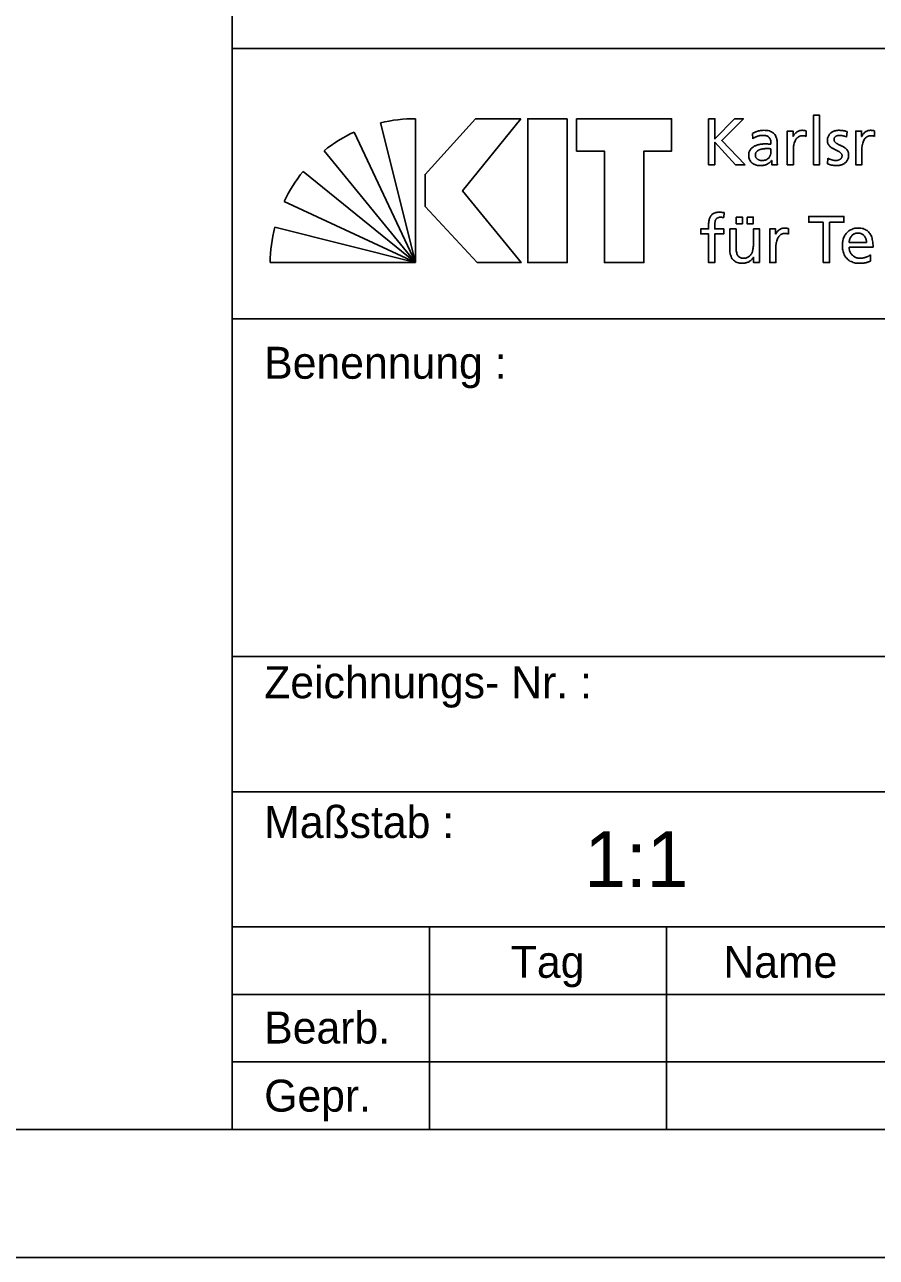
# Model space of a CAD drawing. Extents: x 0 to 420, y 0 to 297.
# Drawn here: x 315 to 368.3, y 0 to 77.2 of the extents above; entities that cross this region are included whole.
import ezdxf

# ---------------------------------------------------------------- set-up
doc = ezdxf.new("R2010")
doc.units = 0
doc.layers.add('90_Plankopf', color=7, linetype='Continuous')

msp = doc.modelspace()

# ---------------------------------------------------------------- linework, layer by layer
at = {"layer": '90_Plankopf'}
for p, q in [((328.001, 75.68), (328.001, 88.37)), ((328.001, 75.68), (412, 75.68)), ((337.275, 71.023), (339.481, 62.276)), ((339.481, 62.276), (339.481, 71.274)), ((357.81, 71.276), (357.81, 68.396)), ((339.481, 62.276), (335.633, 70.442)), ((360.579, 70.352), (360.6, 70.022)), ((363.926, 70.174), (363.926, 70.521)), ((366.457, 70.129), (366.49, 70.468)), ((368.211, 70.174), (368.211, 70.521)), ((362.118, 68.808), (362.118, 69.679)), ((333.744, 69.275), (339.481, 62.276)), ((361.73, 69.399), (361.73, 69.213)), ((365.297, 68.808), (365.277, 68.462)), ((339.481, 62.276), (332.434, 67.976)), ((357.81, 68.396), (358.222, 68.396)), ((359.506, 68.396), (360.108, 68.396)), ((331.24, 66.103), (339.481, 62.276)), ((358.773, 65.083), (358.79, 65.396)), ((339.481, 62.276), (330.658, 64.478)), ((362.827, 64.055), (362.827, 64.402)), ((367.706, 63.531), (366.616, 63.531)), ((366.616, 63.242), (368.119, 63.242)), ((367.958, 62.363), (367.958, 62.751)), ((330.364, 62.276), (339.481, 62.276)), ((328.001, 58.76), (412, 58.76)), ((328.001, 37.61), (412, 37.61)), ((328.001, 29.15), (412, 29.15)), ((328.001, 20.69), (412, 20.69)), ((328.001, 20.69), (412, 20.69)), ((328.001, 20.69), (412, 20.69)), ((328.001, 20.69), (412, 20.69)), ((328.001, 8), (328.001, 20.69)), ((340.353, 20.69), (340.353, 8)), ((355.177, 8), (355.177, 20.69)), ((328.001, 16.46), (370, 16.46)), ((328.001, 12.23), (370, 12.23)), ((328.001, 8), (412, 8)), ((328.001, 8), (411.999, 8))]:
    msp.add_line(p, q, dxfattribs=at)
for points in [[(0, 0), (420, 0), (420, 297), (0, 297)], [(8, 8), (412, 8), (412, 289), (8, 289)], [(346.066, 71.276), (343.236, 71.276), (340.073, 67.789), (340.073, 65.782), (343.338, 62.276), (346.085, 62.276), (342.422, 66.753)], [(348.97, 71.276), (348.97, 62.276), (346.501, 62.276), (346.501, 71.276)], [(349.562, 71.276), (349.562, 69.25), (351.301, 69.25), (351.301, 62.276), (353.771, 62.276), (353.771, 69.25), (355.51, 69.25), (355.51, 71.276)]]:
    msp.add_lwpolyline(points, close=True, dxfattribs=at)
for points in [[(328.001, 20.69), (328.001, 75.68)], [(360.108, 68.396), (358.647, 69.914), (360.001, 71.276), (359.452, 71.276), (358.222, 70.009), (358.222, 71.276), (357.81, 71.276)], [(364.381, 68.396), (364.768, 68.396), (364.768, 71.491), (364.381, 71.491), (364.381, 68.396)], [(363.122, 70.174), (363.113, 70.174), (363.113, 70.5), (362.75, 70.5), (362.75, 68.396), (363.138, 68.396), (363.138, 69.353)], [(367.407, 70.174), (367.398, 70.174), (367.398, 70.5), (367.035, 70.5), (367.035, 68.396), (367.423, 68.396), (367.423, 69.353)], [(358.222, 68.396), (358.222, 69.807), (359.506, 68.396)], [(361.763, 68.668), (361.772, 68.668), (361.772, 68.396), (362.135, 68.396)], [(359.554, 65.116), (359.554, 64.703), (359.942, 64.703), (359.942, 65.116), (359.554, 65.116)], [(360.231, 65.116), (360.231, 64.703), (360.619, 64.703), (360.619, 65.116), (360.231, 65.116)], [(364.99, 62.276), (365.403, 62.276), (365.403, 64.794), (366.298, 64.794), (366.298, 65.157), (364.094, 65.157), (364.094, 64.794), (364.99, 64.794), (364.99, 62.276)], [(357.824, 64.575), (357.824, 64.381), (357.329, 64.381), (357.329, 64.068), (357.824, 64.068), (357.824, 62.276), (358.212, 62.276), (358.212, 64.068), (358.769, 64.068), (358.769, 64.381), (358.212, 64.381), (358.212, 64.608)], [(359.542, 63.292), (359.542, 64.381), (359.154, 64.381), (359.154, 63.131)], [(361.015, 62.276), (361.015, 64.381), (360.627, 64.381), (360.627, 63.407)], [(362.022, 64.055), (362.014, 64.055), (362.014, 64.381), (361.651, 64.381), (361.651, 62.276), (362.039, 62.276), (362.039, 63.234)], [(360.631, 62.611), (360.639, 62.611), (360.639, 62.276), (361.015, 62.276)], [(412, 20.69), (328.001, 20.69)], [(328.001, 20.69), (328.001, 20.69)], [(328.001, 8), (412, 8)]]:
    msp.add_lwpolyline(points, dxfattribs=at)
for centre, start, end in [((339.449, 61.746), 89.80527, 103.18947), ((339.662, 61.808), 115.01261, 128.3968), ((339.816, 61.953), 140.78977, 154.17397), ((339.891, 62.128), 165.72225, 179.10644)]:
    msp.add_arc(centre, 9.528, start, end, dxfattribs=at)
for points in [[(362.118, 69.679), (362.119, 69.87), (362.091, 70.031), (362.033, 70.16), (361.975, 70.289), (361.884, 70.386), (361.759, 70.452), (361.635, 70.517), (361.472, 70.55), (361.272, 70.55), (361.138, 70.549), (361.014, 70.531), (360.898, 70.494), (360.782, 70.458), (360.676, 70.411), (360.579, 70.352)], [(360.6, 70.022), (360.653, 70.066), (360.713, 70.104), (360.779, 70.136), (360.846, 70.168), (360.916, 70.193), (360.99, 70.21), (361.063, 70.228), (361.137, 70.236), (361.21, 70.236), (361.339, 70.236), (361.441, 70.216), (361.518, 70.175), (361.594, 70.134), (361.649, 70.073), (361.682, 69.992), (361.715, 69.909), (361.731, 69.808), (361.73, 69.687)], [(363.926, 70.521), (363.899, 70.527), (363.873, 70.531), (363.849, 70.536), (363.824, 70.54), (363.798, 70.544), (363.769, 70.546), (363.741, 70.549), (363.708, 70.55), (363.67, 70.55), (363.595, 70.549), (363.523, 70.533), (363.452, 70.501), (363.382, 70.469), (363.318, 70.426), (363.261, 70.369), (363.203, 70.313), (363.157, 70.248), (363.122, 70.174)], [(366.49, 70.468), (366.414, 70.491), (366.337, 70.51), (366.259, 70.526), (366.181, 70.541), (366.097, 70.549), (366.007, 70.55), (365.903, 70.55), (365.805, 70.537), (365.716, 70.51), (365.625, 70.484), (365.547, 70.443), (365.48, 70.39), (365.412, 70.337), (365.359, 70.269), (365.322, 70.188), (365.284, 70.107), (365.265, 70.011), (365.264, 69.902), (365.265, 69.818), (365.282, 69.746), (365.315, 69.684), (365.347, 69.623), (365.391, 69.57), (365.445, 69.524), (365.5, 69.48), (365.559, 69.44), (365.623, 69.405), (365.688, 69.37), (365.753, 69.337), (365.817, 69.307), (365.882, 69.276), (365.942, 69.245), (365.995, 69.212), (366.05, 69.18), (366.093, 69.144), (366.126, 69.103), (366.158, 69.063), (366.176, 69.015), (366.176, 68.961), (366.176, 68.905), (366.163, 68.857), (366.139, 68.818), (366.116, 68.78), (366.084, 68.749), (366.045, 68.725), (366.006, 68.702), (365.963, 68.685), (365.917, 68.675), (365.871, 68.665), (365.825, 68.66), (365.78, 68.66), (365.742, 68.66), (365.695, 68.665), (365.639, 68.676), (365.584, 68.687), (365.526, 68.704), (365.466, 68.726), (365.405, 68.748), (365.35, 68.775), (365.297, 68.808)], [(365.277, 68.462), (365.366, 68.416), (365.46, 68.384), (365.558, 68.368), (365.656, 68.352), (365.755, 68.345), (365.854, 68.346), (365.949, 68.346), (366.04, 68.359), (366.127, 68.385), (366.215, 68.412), (366.293, 68.452), (366.363, 68.506), (366.431, 68.559), (366.487, 68.628), (366.527, 68.71), (366.568, 68.793), (366.588, 68.89), (366.589, 69.002), (366.588, 69.098), (366.571, 69.179), (366.539, 69.246), (366.506, 69.312), (366.462, 69.369), (366.408, 69.416), (366.354, 69.462), (366.295, 69.501), (366.23, 69.535), (366.165, 69.568), (366.101, 69.599), (366.036, 69.627), (365.971, 69.656), (365.912, 69.685), (365.858, 69.716), (365.804, 69.748), (365.76, 69.785), (365.727, 69.826), (365.695, 69.869), (365.678, 69.92), (365.677, 69.981), (365.678, 70.038), (365.696, 70.086), (365.729, 70.124), (365.763, 70.162), (365.808, 70.19), (365.864, 70.209), (365.92, 70.228), (365.982, 70.236), (366.048, 70.236), (366.072, 70.236), (366.102, 70.233), (366.139, 70.228), (366.175, 70.221), (366.213, 70.213), (366.254, 70.203), (366.295, 70.193), (366.333, 70.181), (366.369, 70.168), (366.405, 70.156), (366.434, 70.143), (366.457, 70.129)], [(368.211, 70.521), (368.184, 70.527), (368.158, 70.531), (368.134, 70.536), (368.11, 70.54), (368.083, 70.544), (368.054, 70.546), (368.026, 70.549), (367.993, 70.55), (367.955, 70.55), (367.88, 70.549), (367.808, 70.533), (367.737, 70.501), (367.667, 70.469), (367.603, 70.426), (367.546, 70.369), (367.488, 70.313), (367.442, 70.248), (367.407, 70.174)], [(361.73, 69.687), (361.68, 69.69), (361.633, 69.692), (361.589, 69.693), (361.546, 69.694), (361.502, 69.695), (361.459, 69.696), (361.415, 69.696), (361.368, 69.696), (361.318, 69.696), (361.237, 69.696), (361.151, 69.689), (361.063, 69.674), (360.973, 69.66), (360.886, 69.637), (360.801, 69.604), (360.715, 69.571), (360.638, 69.528), (360.569, 69.475), (360.499, 69.421), (360.444, 69.355), (360.403, 69.278), (360.362, 69.199), (360.341, 69.108), (360.34, 69.002), (360.341, 68.85), (360.374, 68.725), (360.439, 68.629), (360.504, 68.532), (360.594, 68.46), (360.71, 68.414), (360.825, 68.369), (360.959, 68.346), (361.111, 68.346), (361.2, 68.347), (361.28, 68.358), (361.35, 68.379), (361.421, 68.399), (361.483, 68.426), (361.536, 68.459), (361.59, 68.492), (361.635, 68.527), (361.673, 68.564), (361.71, 68.601), (361.741, 68.635), (361.763, 68.668)], [(363.138, 69.353), (363.139, 69.53), (363.163, 69.683), (363.21, 69.811), (363.257, 69.939), (363.323, 70.038), (363.409, 70.106), (363.494, 70.176), (363.595, 70.211), (363.712, 70.211), (363.746, 70.212), (363.78, 70.209), (363.818, 70.204), (363.855, 70.199), (363.891, 70.189), (363.926, 70.174)], [(367.423, 69.353), (367.424, 69.53), (367.448, 69.683), (367.495, 69.811), (367.542, 69.939), (367.608, 70.038), (367.694, 70.106), (367.779, 70.176), (367.88, 70.211), (367.997, 70.211), (368.03, 70.212), (368.065, 70.209), (368.103, 70.204), (368.14, 70.199), (368.175, 70.189), (368.211, 70.174)], [(361.73, 69.213), (361.73, 69.108), (361.708, 69.013), (361.664, 68.93), (361.62, 68.847), (361.554, 68.782), (361.467, 68.733), (361.38, 68.685), (361.272, 68.66), (361.144, 68.66), (361.1, 68.66), (361.054, 68.668), (361.008, 68.682), (360.963, 68.697), (360.92, 68.718), (360.882, 68.747), (360.843, 68.777), (360.812, 68.813), (360.789, 68.855), (360.765, 68.897), (360.753, 68.947), (360.752, 69.002), (360.754, 69.076), (360.772, 69.138), (360.808, 69.187), (360.844, 69.236), (360.891, 69.276), (360.949, 69.305), (361.007, 69.335), (361.069, 69.357), (361.135, 69.372), (361.201, 69.386), (361.265, 69.396), (361.326, 69.401), (361.387, 69.405), (361.439, 69.407), (361.483, 69.407), (361.524, 69.407), (361.565, 69.405), (361.607, 69.403), (361.648, 69.401), (361.689, 69.399), (361.73, 69.399)], [(362.135, 68.396), (362.132, 68.416), (362.129, 68.443), (362.126, 68.477), (362.125, 68.511), (362.122, 68.555), (362.121, 68.609), (362.119, 68.663), (362.118, 68.729), (362.118, 68.808)], [(358.79, 65.396), (358.751, 65.402), (358.71, 65.409), (358.668, 65.413), (358.625, 65.418), (358.579, 65.421), (358.53, 65.421), (358.388, 65.42), (358.27, 65.4), (358.178, 65.361), (358.086, 65.321), (358.014, 65.264), (357.962, 65.19), (357.91, 65.116), (357.875, 65.027), (357.854, 64.923), (357.833, 64.819), (357.824, 64.704), (357.824, 64.575)], [(358.212, 64.608), (358.212, 64.68), (358.216, 64.746), (358.224, 64.806), (358.232, 64.867), (358.249, 64.92), (358.275, 64.965), (358.3, 65.01), (358.338, 65.045), (358.388, 65.069), (358.439, 65.094), (358.505, 65.107), (358.588, 65.107), (358.621, 65.107), (358.655, 65.105), (358.688, 65.101), (358.722, 65.097), (358.75, 65.091), (358.773, 65.083)], [(362.827, 64.402), (362.8, 64.407), (362.774, 64.412), (362.75, 64.417), (362.725, 64.421), (362.698, 64.424), (362.67, 64.427), (362.642, 64.429), (362.609, 64.43), (362.571, 64.43), (362.496, 64.43), (362.423, 64.414), (362.352, 64.382), (362.282, 64.35), (362.218, 64.306), (362.161, 64.25), (362.104, 64.193), (362.057, 64.129), (362.022, 64.055)], [(362.039, 63.234), (362.039, 63.411), (362.064, 63.563), (362.11, 63.691), (362.158, 63.819), (362.224, 63.918), (362.31, 63.987), (362.395, 64.057), (362.496, 64.091), (362.612, 64.092), (362.646, 64.093), (362.681, 64.09), (362.718, 64.085), (362.756, 64.079), (362.791, 64.069), (362.827, 64.055)], [(368.119, 63.242), (368.119, 63.412), (368.103, 63.57), (368.072, 63.713), (368.041, 63.858), (367.989, 63.983), (367.918, 64.09), (367.846, 64.197), (367.751, 64.281), (367.631, 64.34), (367.512, 64.399), (367.365, 64.43), (367.19, 64.43), (367.041, 64.43), (366.906, 64.404), (366.785, 64.352), (366.665, 64.3), (366.561, 64.227), (366.474, 64.132), (366.387, 64.037), (366.321, 63.925), (366.275, 63.795), (366.228, 63.666), (366.205, 63.523), (366.204, 63.366), (366.204, 63.194), (366.225, 63.038), (366.269, 62.899), (366.312, 62.759), (366.379, 62.64), (366.469, 62.54), (366.558, 62.439), (366.671, 62.362), (366.808, 62.309), (366.945, 62.254), (367.107, 62.228), (367.293, 62.227), (367.408, 62.228), (367.506, 62.235), (367.587, 62.25), (367.667, 62.265), (367.737, 62.283), (367.797, 62.304), (367.855, 62.324), (367.909, 62.344), (367.958, 62.363)], [(366.616, 63.531), (366.623, 63.6), (366.639, 63.668), (366.664, 63.737), (366.688, 63.806), (366.722, 63.869), (366.768, 63.926), (366.812, 63.984), (366.869, 64.029), (366.937, 64.064), (367.006, 64.098), (367.087, 64.116), (367.182, 64.117), (367.266, 64.116), (367.34, 64.101), (367.404, 64.071), (367.47, 64.04), (367.524, 63.999), (367.569, 63.945), (367.614, 63.891), (367.648, 63.829), (367.671, 63.759), (367.694, 63.688), (367.706, 63.612), (367.706, 63.531)], [(360.627, 63.407), (360.627, 63.279), (360.615, 63.161), (360.589, 63.055), (360.564, 62.95), (360.525, 62.859), (360.473, 62.782), (360.421, 62.705), (360.354, 62.646), (360.273, 62.604), (360.193, 62.562), (360.097, 62.541), (359.987, 62.54), (359.875, 62.547), (359.786, 62.579), (359.721, 62.635), (359.656, 62.692), (359.61, 62.774), (359.582, 62.883), (359.554, 62.992), (359.541, 63.128), (359.542, 63.292)], [(359.154, 63.131), (359.154, 62.941), (359.181, 62.78), (359.237, 62.645), (359.293, 62.51), (359.379, 62.407), (359.496, 62.335), (359.612, 62.264), (359.761, 62.228), (359.942, 62.227), (360.04, 62.228), (360.135, 62.243), (360.225, 62.273), (360.315, 62.304), (360.396, 62.348), (360.466, 62.405), (360.537, 62.462), (360.592, 62.531), (360.631, 62.611)], [(367.958, 62.751), (367.933, 62.731), (367.899, 62.709), (367.852, 62.685), (367.806, 62.661), (367.754, 62.638), (367.694, 62.616), (367.634, 62.594), (367.572, 62.576), (367.506, 62.562), (367.44, 62.548), (367.374, 62.541), (367.309, 62.54), (367.217, 62.541), (367.13, 62.558), (367.046, 62.592), (366.964, 62.625), (366.889, 62.673), (366.825, 62.735), (366.761, 62.797), (366.71, 62.871), (366.673, 62.957), (366.636, 63.043), (366.617, 63.138), (366.616, 63.242)]]:
    msp.add_open_spline(points, degree=3, dxfattribs=at)

# ---------------------------------------------------------------- texts
for s, height, p in [('Benennung :', 2, (330, 55)), ('Zeichnungs- Nr. :', 2, (330, 35)), ('Maßstab :', 2, (330, 26.25)), ('1:1     ', 3.4999, (350.048, 23.175)), ('Tag', 2, (345.441, 17.5)), ('Name', 2, (358.75, 17.5)), ('Bearb.', 2, (330, 13.385)), ('Gepr.', 2, (330, 9.122))]:
    msp.add_text(s, height=height, dxfattribs=at).set_placement(p)

doc.saveas('drawing.dxf')
